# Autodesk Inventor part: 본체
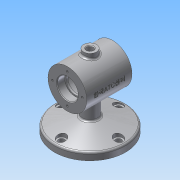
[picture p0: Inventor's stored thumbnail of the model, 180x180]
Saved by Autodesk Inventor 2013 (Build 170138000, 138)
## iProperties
Created: 2018-12
Part Number: 본체
Material: 알루미늄 6061
Document SubType Name: Modeling
Designer: Administrator
Density: 2.71 g/cm^3
Mass: 687.368 g
Surface Area: 556.054 cm^2
Volume: 253.641 cm^3
Author: Administrator
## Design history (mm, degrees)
sketch "스케치1"
  geometry: L1 (0, 16)-(0, 30); L2 (0, 30)-(35, 30); L3 (35, 30)-(35, 25); L4 (35, 25)-(15, 25); L5 (15, 25)-(15, 14); L6 (15, 14)-(12, 14); L7 (12, 14)-(12, 16); L8 (12, 16)-(0, 16); L9 (0, 0)-(35, 0)
  constraints: 18 end point, 6 parallel, 2 point on line, 1 perpendicular, 1 vertical
  dimensions: "d0" = 35 distance of L1.end L2.end; "d2" = 60 diameter of L2 L9; "d3" = 32 diameter of L8 L9; "d4" = 28 diameter of L6 L9; "d5" = 50 diameter of L4 L9; "d6" = 12 distance of L7.end L1.start; "d7" = 20 distance of L3.end L4.end
revolve "회전1" sketch "스케치1" stored, may be unused: angle "d8" = 90 deg
sketch "스케치2"
  geometry: 2 further points
  constraints: 1 vertical alignment
  dimensions: "d9" = 23 distance of point (0, 23) point (0, 0)
hole "구멍1" sketch "스케치2" at (0, 23) diameter "d10" = 3.242; stored, may be unused: countersink angle "d14" = 90 deg, drill point angle "d16" = 118 deg; dims "d11" = 8, "d12" = 4, "d13" = 2, "d15" = 10
node "작업 평면1"
node "작업 평면3"
sketch "스케치3"
  geometry: C1 r 55 at (-35, 0); 1 further point
  constraints: 1 centre point, 1 horizontal alignment
  dimensions: "d22" = 110 diameter of C1; "d23" = 35 distance of C1.centre point (0, 0)
extrude "돌출1" join sketch "스케치3" distance "d24" = 11; taper "d25" = 0 deg
sketch "스케치4"
  geometry: C1 r 55 at (0, 0) reference; C2 r 12 at (0, 0); 1 further point
  constraints: 1 centre point, 1 coincident
  dimensions: "d26" = 24 diameter of C2
extrude "돌출2" join sketch "스케치4" stored distance "d27" = 11; taper "d28" = 0 deg
sketch "스케치5"
  geometry: C1 r 55 at (0, 0) reference; C2 r 55 at (0, 0); 1 further point
  constraints: 1 centre point, 1 coincident
  dimensions: "d29" = 110 diameter of C2
extrude "돌출3" join sketch "스케치5" distance "d30" = 15; taper "d31" = -75 deg
sketch "스케치7"
  geometry: C1 r 4.5 at (0, -44); C2 r 55 at (0, 0) reference; 1 further point
  constraints: 1 centre point, 1 vertical alignment
  dimensions: "d40" = 9 diameter of C1; "d41" = 44 distance of C1.centre C2.centre
extrude "돌출4" cut sketch "스케치7" distance "d42" = 10; taper "d43" = 0 deg
sketch "스케치8"
  geometry: C1 r 4.5 at (0, 0) reference; C2 r 7 at (0, 0); 1 further point
  constraints: 1 centre point, 1 coincident
  dimensions: "d44" = 14 diameter of C2
extrude "돌출5" cut sketch "스케치8" stored distance "d45" = 10; taper "d46" = 0 deg
node "작업 평면4"
sketch "스케치9"
  geometry: L1 (0, 30)-(0, -30) reference; C1 r 10 at (-35, 0); 1 further point
  constraints: 1 centre point, 1 horizontal alignment
  dimensions: "d51" = 20 diameter of C1; "d52" = 35 distance from line of C1.centre L1
extrude "돌출6" join sketch "스케치9" stored distance "d53" = 10; taper "d54" = 0 deg
hole "구멍3" diameter "d57" = 10; stored, may be unused: countersink angle "d61" = 90 deg, drill point angle "d63" = 118 deg; dims "d55" = 10, "d56" = 10, "d58" = 14, "d59" = 9, "d60" = 10, "d62" = 10
node "작업 평면5"
sketch "스케치10"
  geometry: L1 (0, 30)-(70, 30) reference; L2 (0, -30)-(0, 30) reference; 2 further points
  constraints: 1 other
  dimensions: "d65" = 30 distance from line of L1 point (35, 0); "d66" = 35 distance from line of L2 point (35, 0)
feature "엠보싱1" sketch "스케치10" dims "d67" = 0.5, "d68" = 0
fillet "모깎기1" dims "d69" = 0.3
fillet "모깎기2" dims "d70" = 3
fillet "모깎기3" dims "d71" = 3
chamfer "모따기1" distance "d72" = 1; stored, may be unused: second distance "d73" = 2, angle "d74" = 45 deg
node "솔리드1"
pattern_circular "원형 패턴1" dims angle "d18" = 360 deg
mirror "대칭1"
pattern_circular "원형 패턴2" dims angle "d48" = 360 deg
node "작업 평면2"
other parameters: "d20" = 35, "d21" = -75, "d50" = 37, "d64" = 106.5
